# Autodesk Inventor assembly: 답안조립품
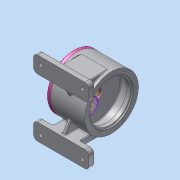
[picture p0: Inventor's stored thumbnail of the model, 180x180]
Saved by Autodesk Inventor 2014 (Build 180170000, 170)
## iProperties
Created: 2025-12
Part Number: 답안조립품
Document SubType Name: Assembly
Designer: dg
Author: dg
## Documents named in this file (17)
- C:\Users\dg\Desktop\751203V1010\답안조립품.iam
- C:\Users\dg\Desktop\751203V1010\본체.ipt
- C:\Users\dg\Desktop\751203V1010\가져온 구성요소\출력 축\출력 축.ipt
- C:\Users\dg\Desktop\751203V1010\가져온 구성요소\깊은 홈 볼 베어링 6005\깊은 홈 볼 베어링 6005.ipt
- C:\Users\dg\Desktop\751203V1010\가져온 구성요소\커버\커버.ipt
- C:\Users\dg\Desktop\751203V1010\가져온 구성요소\오일 실 25 40 8\오일 실 25 40 8.ipt
- C:\Users\dg\Desktop\751203V1010\가져온 구성요소\평행 키 6x6x16\평행 키 6x6x16.ipt
- C:\Users\dg\Desktop\751203V1010\가져온 구성요소\종동 기어\종동 기어.ipt
- C:\Users\dg\Desktop\751203V1010\가져온 구성요소\칼라 2\칼라 2.ipt
- C:\Users\dg\Desktop\751203V1010\가져온 구성요소\깊은 홈 볼 베어링 6004\깊은 홈 볼 베어링 6004.ipt
- C:\Users\dg\Desktop\751203V1010\가져온 구성요소\6각 머리 볼트 M8x20\6각 머리 볼트 M8x20.ipt
- C:\Users\dg\Desktop\751203V1010\가져온 구성요소\C형 멈춤링 구멍용 42\C형 멈춤링 구멍용 42.ipt
- C:\Users\dg\Desktop\751203V1010\가져온 구성요소\기어 축\기어 축.ipt
- C:\Users\dg\Desktop\751203V1010\가져온 구성요소\칼라 1\칼라 1.ipt
- C:\Users\dg\Desktop\751203V1010\가져온 구성요소\구동 기어\구동 기어.ipt
- C:\Users\dg\Desktop\751203V1010\가져온 구성요소\6각 구멍붙이 볼트 M4x10\6각 구멍붙이 볼트 M4x10.ipt
- C:\Users\dg\Desktop\751203V1010\가져온 구성요소\엔드 캡\엔드 캡.ipt
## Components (9 placed, 4 different names)
1. C형 멈춤링 구멍용 42:1
2. 구동 기어:1
3. 6각 구멍붙이 볼트 M4x10:1
4. 6각 머리 볼트 M8x20:1
5. 6각 머리 볼트 M8x20:2
6. 6각 머리 볼트 M8x20:3
7. 6각 머리 볼트 M8x20:4
8. 6각 머리 볼트 M8x20:5
9. 6각 머리 볼트 M8x20:6
